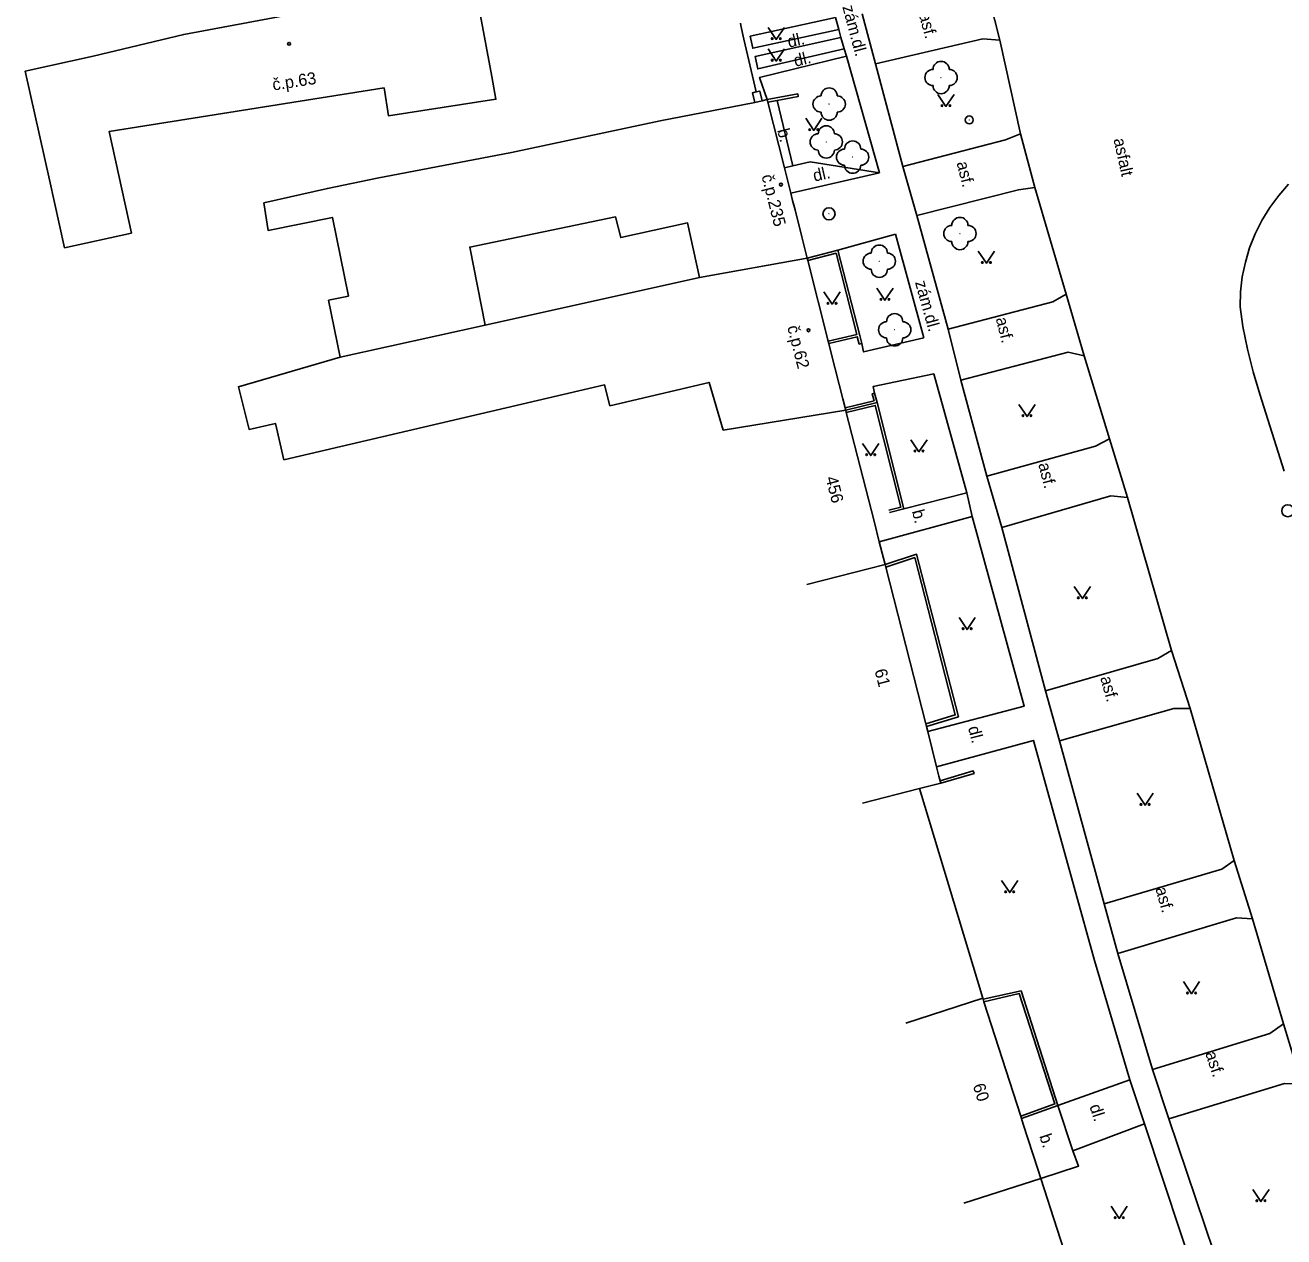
# Model space of a CAD drawing. Extents: x -577457 to -568404, y -1208466 to -1201387.
# Drawn here: x -575431.7 to -575353.9, y -1204210.4 to -1204135.5 of the extents above; entities that cross this region are included whole.
import ezdxf

# ---------------------------------------------------------------- set-up
doc = ezdxf.new("R2010")
doc.units = 0
for name, color, linetype in [('BUDOVY_MĚŘ', 7, 'Continuous'), ('BUDOVY_NEMĚŘ', 7, 'Continuous'), ('MAP_ZN_BP', 7, 'Continuous'), ('POMOC_POPIS', 7, 'Continuous'), ('ROZHRANÍ_PLOCH', 7, 'Continuous'), ('ZELEŇ', 7, 'Continuous'), ('ZN_BUDOV', 7, 'Continuous'), ('ZN_DOPLŇKOVÉ', 7, 'Continuous'), ('ZN_KULTUR', 7, 'Continuous'), ('Č_POPIS_ORIENT', 7, 'Continuous')]:
    doc.layers.add(name, color=color, linetype=linetype)

msp = doc.modelspace()

# ---------------------------------------------------------------- linework, layer by layer
at = {"layer": 'BUDOVY_MĚŘ'}
for points in [[(-575386.12, -1204140.16), (-575386.56, -1204140.27)], [(-575385.81, -1204140.08), (-575386.12, -1204140.16)], [(-575385.77, -1204140.24), (-575385.81, -1204140.08)], [(-575384.74, -1204144.31), (-575385.77, -1204140.24)], [(-575384.33, -1204145.86), (-575384.53, -1204145.13)], [(-575384.23, -1204146.31), (-575384.33, -1204145.86)], [(-575383.33, -1204149.88), (-575383.51, -1204149.15)], [(-575383.29, -1204150.03), (-575383.33, -1204149.88)], [(-575382.03, -1204155.02), (-575383.29, -1204150.03)], [(-575381.99, -1204155.16), (-575382.03, -1204155.02)], [(-575381.82, -1204155.84), (-575381.99, -1204155.16)], [(-575380.99, -1204159.13), (-575381.13, -1204158.57)], [(-575380.95, -1204159.28), (-575380.99, -1204159.13)], [(-575380.91, -1204159.42), (-575380.95, -1204159.28)], [(-575379.19, -1204166.14), (-575380.91, -1204159.42)], [(-575378.51, -1204168.81), (-575378.61, -1204168.42)], [(-575383.36, -1204170.05), (-575378.51, -1204168.81)], [(-575378.51, -1204168.81), (-575378.47, -1204168.97)], [(-575378.47, -1204168.97), (-575376, -1204178.66)], [(-575376, -1204178.66), (-575375.96, -1204178.82)], [(-575375.96, -1204178.82), (-575375.88, -1204179.14)], [(-575375.07, -1204182.33), (-575376.38, -1204182.66)], [(-575375.19, -1204181.89), (-575375.11, -1204182.18)], [(-575375.11, -1204182.18), (-575375.07, -1204182.33)], [(-575376.38, -1204182.66), (-575379.92, -1204183.56)], [(-575372.48, -1204195.62), (-575377.24, -1204197.15)], [(-575372.46, -1204195.68), (-575372.48, -1204195.62)], [(-575372.41, -1204195.83), (-575372.46, -1204195.68)], [(-575370.13, -1204202.9), (-575372.41, -1204195.83)], [(-575370.08, -1204203.05), (-575370.13, -1204202.9)], [(-575369.97, -1204203.39), (-575370.08, -1204203.05)], [(-575368.89, -1204206.75), (-575369.07, -1204206.18)], [(-575373.65, -1204208.28), (-575368.89, -1204206.75)], [(-575366.26, -1204213.16), (-575366.4, -1204212.83), (-575366.87, -1204213.02), (-575368.89, -1204206.75)]]:
    msp.add_lwpolyline(points, dxfattribs=at)
at = {"layer": 'BUDOVY_NEMĚŘ'}
for points in [[(-575404.09, -1204132.73), (-575403.88, -1204133.01), (-575402.82, -1204138.65), (-575402.57, -1204140.06), (-575409.22, -1204141.08), (-575409.48, -1204139.36), (-575426.48, -1204142.06), (-575425.1, -1204148.33), (-575429.23, -1204149.24), (-575430.17, -1204145.04), (-575431.67, -1204138.32), (-575427.47, -1204137.4), (-575421.87, -1204136.06), (-575404.09, -1204132.73)], [(-575412.19, -1204156), (-575412.91, -1204152.48), (-575411.69, -1204152.23), (-575412.68, -1204147.36), (-575416.65, -1204148.17), (-575416.91, -1204146.47), (-575412.99, -1204145.57), (-575409.91, -1204144.94), (-575401.61, -1204143.36), (-575392.41, -1204141.39), (-575386.56, -1204140.27)], [(-575389.99, -1204151.08), (-575390.72, -1204147.7), (-575394.85, -1204148.61), (-575395.17, -1204147.33), (-575404.19, -1204149.2), (-575403.23, -1204154.02)], [(-575389.99, -1204151.08), (-575383.33, -1204149.88)], [(-575403.23, -1204154.02), (-575389.99, -1204151.08)], [(-575412.19, -1204156), (-575403.23, -1204154.02)], [(-575388.52, -1204160.52), (-575389.39, -1204157.56), (-575395.52, -1204159), (-575395.85, -1204157.72), (-575415.68, -1204162.34), (-575416.2, -1204160.09), (-575417.83, -1204160.47), (-575418.49, -1204157.83), (-575412.19, -1204156)], [(-575380.95, -1204159.28), (-575388.52, -1204160.52)]]:
    msp.add_lwpolyline(points, dxfattribs=at)
at = {"layer": 'MAP_ZN_BP'}
for centre, radius in [((-575381.98, -1204147.14), 0.375), ((-575381.98, -1204147.14), 0.0005), ((-575353.62, -1204165.491), 0.375)]:
    msp.add_circle(centre, radius, dxfattribs=at)
at = {"layer": 'ROZHRANÍ_PLOCH'}
for points in [[(-575371.42, -1204136.42), (-575372.34, -1204132.74)], [(-575381.58, -1204135.02), (-575386.85, -1204136.16), (-575386.69, -1204136.91), (-575381.37, -1204135.75)], [(-575381.37, -1204135.75), (-575381.58, -1204135.02)], [(-575379.93, -1204134.78), (-575379.1, -1204137.87)], [(-575381.25, -1204136.24), (-575381.37, -1204135.75)], [(-575381.25, -1204136.24), (-575386.55, -1204137.43), (-575386.39, -1204138.19), (-575381.04, -1204136.94)], [(-575381.04, -1204136.94), (-575381.25, -1204136.24)], [(-575371.42, -1204136.42), (-575372.48, -1204136.33), (-575379.1, -1204137.87)], [(-575370.14, -1204142.21), (-575371.42, -1204136.42)], [(-575380.89, -1204137.4), (-575386.27, -1204138.71), (-575385.81, -1204140.08)], [(-575380.89, -1204137.4), (-575381.04, -1204136.94)], [(-575378.86, -1204144.61), (-575380.89, -1204137.4)], [(-575379.1, -1204137.87), (-575377.41, -1204144.21)], [(-575384.22, -1204144.18), (-575385.19, -1204140.13)], [(-575377.41, -1204144.21), (-575371.07, -1204142.57), (-575370.14, -1204142.21)], [(-575369.26, -1204145.51), (-575370.14, -1204142.21)], [(-575384.74, -1204144.31), (-575384.22, -1204144.18)], [(-575384.22, -1204144.18), (-575383.14, -1204143.92), (-575378.86, -1204144.61)], [(-575377.41, -1204144.21), (-575376.56, -1204147.25)], [(-575378.86, -1204144.61), (-575384.33, -1204145.86)], [(-575376.56, -1204147.25), (-575370.27, -1204145.67), (-575369.26, -1204145.51)], [(-575369.26, -1204145.51), (-575367.32, -1204152.1)], [(-575353.85, -1204163.04), (-575355.34, -1204158.29), (-575355.77, -1204156.91), (-575356.12, -1204155.51), (-575356.4, -1204154.1), (-575356.57, -1204152.89), (-575356.54, -1204151.96), (-575356.43, -1204151.04), (-575356.24, -1204150.13), (-575355.98, -1204149.25), (-575355.63, -1204148.38), (-575355.22, -1204147.55), (-575354.73, -1204146.76), (-575354.18, -1204146.02), (-575353.57, -1204145.32)], [(-575374.61, -1204154.27), (-575376.56, -1204147.25)], [(-575381.44, -1204149.39), (-575377.87, -1204148.4)], [(-575377.87, -1204148.4), (-575376.12, -1204154.81)], [(-575367.32, -1204152.1), (-575368.15, -1204152.59), (-575374.61, -1204154.27)], [(-575366.21, -1204155.91), (-575367.32, -1204152.1)], [(-575374.61, -1204154.27), (-575373.84, -1204157.42)], [(-575376.12, -1204154.81), (-575379.84, -1204155.68), (-575379.96, -1204155.15)], [(-575373.84, -1204157.42), (-575367.2, -1204155.69), (-575366.21, -1204155.91)], [(-575364.65, -1204161.05), (-575366.21, -1204155.91)], [(-575375.49, -1204157.03), (-575379.26, -1204157.82), (-575379.17, -1204158.22)], [(-575373.46, -1204164.38), (-575375.49, -1204157.03)], [(-575372.22, -1204163.36), (-575373.84, -1204157.42)], [(-575364.65, -1204161.05), (-575365.5, -1204161.51), (-575372.22, -1204163.36)], [(-575363.52, -1204164.67), (-575364.65, -1204161.05)], [(-575372.22, -1204163.36), (-575371.29, -1204166.53)], [(-575373.46, -1204164.38), (-575377.35, -1204165.37)], [(-575373.13, -1204165.84), (-575373.46, -1204164.38)], [(-575371.29, -1204166.53), (-575364.56, -1204164.57), (-575363.52, -1204164.67)], [(-575363.52, -1204164.67), (-575360.81, -1204174.13)], [(-575373.13, -1204165.84), (-575378.87, -1204167.41)], [(-575373.13, -1204165.84), (-575369.91, -1204177.57), (-575375.88, -1204179.14)], [(-575368.6, -1204176.62), (-575371.29, -1204166.53)], [(-575360.81, -1204174.13), (-575361.65, -1204174.63), (-575368.6, -1204176.62)], [(-575359.65, -1204177.72), (-575360.81, -1204174.13)], [(-575368.6, -1204176.62), (-575367.74, -1204179.7)], [(-575367.74, -1204179.7), (-575360.67, -1204177.72), (-575359.65, -1204177.72)], [(-575356.94, -1204187.1), (-575359.65, -1204177.72)], [(-575363.39, -1204200.66), (-575365.56, -1204193.29), (-575369.34, -1204179.68), (-575375.33, -1204181.32)], [(-575364.98, -1204189.78), (-575367.74, -1204179.7)], [(-575356.94, -1204187.1), (-575357.69, -1204187.65), (-575364.98, -1204189.78)], [(-575355.81, -1204190.71), (-575356.94, -1204187.1)], [(-575364.98, -1204189.78), (-575364.12, -1204192.85)], [(-575364.12, -1204192.85), (-575356.79, -1204190.65), (-575355.81, -1204190.71)], [(-575353.88, -1204197.2), (-575355.81, -1204190.71)], [(-575361.99, -1204200.01), (-575364.12, -1204192.85)], [(-575353.88, -1204197.2), (-575354.74, -1204197.79), (-575361.99, -1204200.01)], [(-575352.75, -1204200.93), (-575353.88, -1204197.2)], [(-575361.99, -1204200.01), (-575360.98, -1204203.06)], [(-575363.39, -1204200.66), (-575367.83, -1204202.24)], [(-575362.48, -1204203.38), (-575363.39, -1204200.66)], [(-575360.98, -1204203.06), (-575353.83, -1204200.89), (-575352.75, -1204200.93)], [(-575367.83, -1204202.24), (-575366.9, -1204205.05)], [(-575362.48, -1204203.38), (-575366.9, -1204205.05)], [(-575357.95, -1204217.05), (-575362.48, -1204203.38)], [(-575356.53, -1204216.26), (-575360.98, -1204203.06)], [(-575366.9, -1204205.05), (-575366.55, -1204205.99), (-575368.89, -1204206.75)]]:
    msp.add_lwpolyline(points, dxfattribs=at)
at = {"layer": 'ZELEŇ'}
for centre in [(-575375.05, -1204138.72), (-575381.97, -1204140.36), (-575382.15, -1204142.7), (-575380.52, -1204143.64), (-575373.89, -1204148.36), (-575378.87, -1204150.07), (-575377.92, -1204154.31)]:
    msp.add_circle(centre, 0.0005, dxfattribs=at)
for centre, start, end in [((-575375.05, -1204138.22), 0, 179.99999), ((-575375.55, -1204138.72), 89.99999, 269.99999), ((-575374.55, -1204138.72), 270, 89.99999), ((-575381.97, -1204139.86), 0, 179.99999), ((-575375.05, -1204139.22), 179.99999, 359.99999), ((-575382.47, -1204140.36), 89.99999, 269.99999), ((-575381.47, -1204140.36), 270, 89.99999), ((-575381.97, -1204140.86), 179.99999, 359.99999), ((-575382.15, -1204142.2), 0, 179.99999), ((-575382.65, -1204142.7), 89.99999, 269.99999), ((-575381.65, -1204142.7), 270, 89.99999), ((-575380.52, -1204143.14), 0, 179.99999), ((-575382.15, -1204143.2), 179.99999, 359.99999), ((-575381.02, -1204143.64), 89.99999, 269.99999), ((-575380.02, -1204143.64), 270, 89.99999), ((-575380.52, -1204144.14), 179.99999, 359.99999), ((-575373.89, -1204147.86), 0, 179.99999), ((-575374.39, -1204148.36), 89.99999, 269.99999), ((-575373.39, -1204148.36), 270, 89.99999), ((-575378.87, -1204149.57), 0, 179.99999), ((-575373.89, -1204148.86), 179.99999, 359.99999), ((-575379.37, -1204150.07), 89.99999, 269.99999), ((-575378.37, -1204150.07), 270, 89.99999), ((-575378.87, -1204150.57), 179.99999, 359.99999), ((-575377.92, -1204153.81), 0, 179.99999), ((-575378.42, -1204154.31), 89.99999, 269.99999), ((-575377.42, -1204154.31), 270, 89.99999), ((-575377.92, -1204154.81), 179.99999, 359.99999)]:
    msp.add_arc(centre, 0.5, start, end, dxfattribs=at)
at = {"layer": 'ZN_BUDOV'}
for centre in [(-575415.36, -1204136.64), (-575384.95, -1204145.34), (-575383.25, -1204154.34)]:
    msp.add_circle(centre, 0.0875, dxfattribs=at)
at = {"layer": 'ZN_DOPLŇKOVÉ'}
for points in [[(-575387.46, -1204135.37), (-575387.43, -1204135.5)], [(-575387.43, -1204135.5), (-575387.24, -1204136.34)], [(-575387.24, -1204136.34), (-575386.48, -1204139.61)], [(-575386.56, -1204140.27), (-575386.7, -1204139.66), (-575386.48, -1204139.61)], [(-575386.48, -1204139.61), (-575386.26, -1204139.56), (-575386.12, -1204140.16)], [(-575385.81, -1204140.08), (-575383.91, -1204139.73), (-575383.88, -1204139.89), (-575385.19, -1204140.13)], [(-575385.19, -1204140.13), (-575385.77, -1204140.24)], [(-575384.53, -1204145.13), (-575384.74, -1204144.31)], [(-575384.08, -1204146.9), (-575384.23, -1204146.31)], [(-575383.66, -1204148.56), (-575384.08, -1204146.9)], [(-575383.51, -1204149.15), (-575383.66, -1204148.56)], [(-575383.33, -1204149.88), (-575381.44, -1204149.39)], [(-575383.29, -1204150.03), (-575381.54, -1204149.58), (-575380.26, -1204154.59), (-575382.03, -1204155.02)], [(-575381.44, -1204149.39), (-575380.08, -1204154.67)], [(-575380.08, -1204154.67), (-575379.96, -1204155.15), (-575380.11, -1204155.19), (-575380.23, -1204154.74), (-575381.99, -1204155.16)], [(-575381.13, -1204158.57), (-575381.82, -1204155.84)], [(-575379.01, -1204158.8), (-575379.17, -1204158.22), (-575379.31, -1204158.26), (-575379.19, -1204158.69), (-575380.99, -1204159.13)], [(-575380.95, -1204159.28), (-575379.01, -1204158.8)], [(-575380.91, -1204159.42), (-575379.12, -1204158.98), (-575377.54, -1204165.26), (-575378.29, -1204165.46)], [(-575379.01, -1204158.8), (-575377.35, -1204165.37)], [(-575377.35, -1204165.37), (-575378.25, -1204165.6)], [(-575378.87, -1204167.41), (-575379.19, -1204166.14)], [(-575378.61, -1204168.42), (-575378.87, -1204167.41)], [(-575378.51, -1204168.81), (-575376.57, -1204168.18), (-575373.98, -1204178.22), (-575375.96, -1204178.82)], [(-575378.47, -1204168.97), (-575376.68, -1204168.39), (-575374.18, -1204178.11), (-575376, -1204178.66)], [(-575375.88, -1204179.14), (-575375.33, -1204181.32)], [(-575375.33, -1204181.32), (-575375.19, -1204181.89)], [(-575375.07, -1204182.33), (-575373.01, -1204181.72), (-575373.06, -1204181.57), (-575375.11, -1204182.18)], [(-575376.38, -1204182.66), (-575372.48, -1204195.62)], [(-575372.46, -1204195.68), (-575370.11, -1204195.16), (-575367.83, -1204202.24)], [(-575372.41, -1204195.83), (-575370.22, -1204195.33), (-575368.02, -1204202.15), (-575370.13, -1204202.9)], [(-575367.83, -1204202.24), (-575370.08, -1204203.05)], [(-575369.07, -1204206.18), (-575369.97, -1204203.39)]]:
    msp.add_lwpolyline(points, dxfattribs=at)
for radius in [0.25, 0.0005]:
    msp.add_circle((-575373.311, -1204141.34), radius, dxfattribs=at)
at = {"layer": 'ZN_KULTUR'}
for points in [[(-575385.74, -1204135.62), (-575385.24, -1204136.37), (-575384.74, -1204135.62)], [(-575385.74, -1204136.95), (-575385.24, -1204137.7), (-575384.74, -1204136.95)], [(-575375.25, -1204139.76), (-575374.75, -1204140.51), (-575374.25, -1204139.76)], [(-575383.42, -1204141.24), (-575382.92, -1204141.99), (-575382.42, -1204141.24)], [(-575372.75, -1204149.45), (-575372.25, -1204150.2), (-575371.75, -1204149.45)], [(-575382.29, -1204151.97), (-575381.79, -1204152.72), (-575381.29, -1204151.97)], [(-575379.02, -1204151.73), (-575378.52, -1204152.48), (-575378.02, -1204151.73)], [(-575370.24, -1204158.92), (-575369.74, -1204159.67), (-575369.24, -1204158.92)], [(-575379.9, -1204161.33), (-575379.4, -1204162.08), (-575378.9, -1204161.33)], [(-575376.92, -1204161.1), (-575376.42, -1204161.85), (-575375.92, -1204161.1)], [(-575366.82, -1204170.17), (-575366.32, -1204170.92), (-575365.82, -1204170.17)], [(-575373.94, -1204172.08), (-575373.44, -1204172.83), (-575372.94, -1204172.08)], [(-575362.94, -1204182.94), (-575362.44, -1204183.69), (-575361.94, -1204182.94)], [(-575371.31, -1204188.34), (-575370.81, -1204189.09), (-575370.31, -1204188.34)], [(-575360.07, -1204194.59), (-575359.57, -1204195.34), (-575359.07, -1204194.59)], [(-575355.78, -1204207.43), (-575355.28, -1204208.18), (-575354.78, -1204207.43)], [(-575364.54, -1204208.47), (-575364.04, -1204209.22), (-575363.54, -1204208.47)]]:
    msp.add_lwpolyline(points, dxfattribs=at)
for centre in [(-575385.49, -1204136.32), (-575384.99, -1204136.32), (-575385.49, -1204137.65), (-575384.99, -1204137.65), (-575375, -1204140.46), (-575374.5, -1204140.46), (-575383.17, -1204141.94), (-575382.67, -1204141.94), (-575372.5, -1204150.15), (-575372, -1204150.15), (-575382.04, -1204152.67), (-575381.54, -1204152.67), (-575378.77, -1204152.43), (-575378.27, -1204152.43), (-575369.99, -1204159.62), (-575369.49, -1204159.62), (-575379.65, -1204162.03), (-575379.15, -1204162.03), (-575376.67, -1204161.8), (-575376.17, -1204161.8), (-575366.57, -1204170.87), (-575366.07, -1204170.87), (-575373.69, -1204172.78), (-575373.19, -1204172.78), (-575362.69, -1204183.64), (-575362.19, -1204183.64), (-575371.06, -1204189.04), (-575370.56, -1204189.04), (-575359.82, -1204195.29), (-575359.32, -1204195.29), (-575355.53, -1204208.13), (-575355.03, -1204208.13), (-575364.29, -1204209.17), (-575363.79, -1204209.17)]:
    msp.add_circle(centre, 0.05, dxfattribs=at)

# ---------------------------------------------------------------- texts
at = {"layer": 'POMOC_POPIS'}
for s, rotation, p in [('zám.dl.', 284.92578, (-575381.16, -1204134.35)), ('asf.', 284.95002, (-575376.43, -1204134.82)), ('dl.', 12.30054, (-575384.46, -1204136.88)), ('dl.', 13.68487, (-575384.06, -1204138.06)), ('b.', 284.20173, (-575385.19, -1204141.97)), ('asfalt', 282.4659, (-575364.4, -1204142.54)), ('dl.', 12.87218, (-575382.88, -1204145.16)), ('asf.', 284.18002, (-575374.1, -1204143.99)), ('zám.dl.', 285.52412, (-575376.67, -1204151.37)), ('asf.', 284.26, (-575371.68, -1204153.62)), ('asf.', 284.26, (-575369.05, -1204162.61)), ('b.', 284.31999, (-575376.86, -1204165.52)), ('asf.', 285.48997, (-575365.22, -1204175.81)), ('dl.', 284.26, (-575373.39, -1204178.89)), ('asf.', 285.61001, (-575361.81, -1204188.84)), ('asf.', 288.29999, (-575358.73, -1204199.02)), ('dl.', 287.88998, (-575365.89, -1204202.29)), ('b.', 287.88998, (-575368.99, -1204204.13))]:
    msp.add_text(s, height=0.75, rotation=rotation, dxfattribs=at).set_placement(p)
at = {"layer": 'Č_POPIS_ORIENT'}
for s, rotation, p in [('č.p.63', 9.02454, (-575416.33, -1204139.53)), ('č.p.235', 284.18002, (-575386.16, -1204144.8)), ('č.p.62', 284.26, (-575384.57, -1204154.13)), ('456', 284.31999, (-575382.2, -1204163.46)), ('61', 284.26, (-575379.17, -1204175.36)), ('60', 287.88998, (-575373.1, -1204201.01))]:
    msp.add_text(s, height=0.75, rotation=rotation, dxfattribs=at).set_placement(p)

doc.saveas('drawing.dxf')
